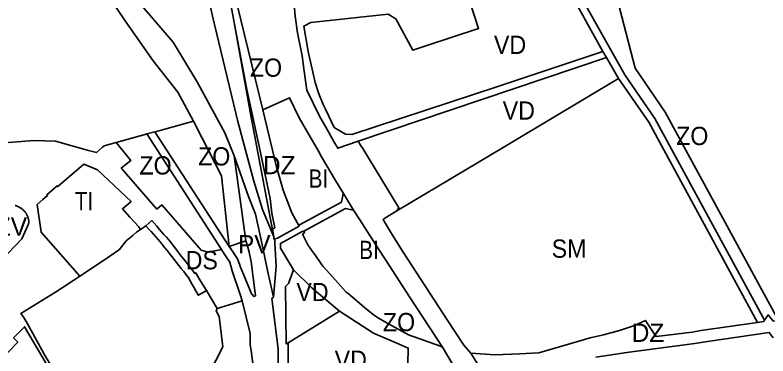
# Model space of a CAD drawing. Extents: x -650451 to -642268, y -1075216 to -1066610.
# Drawn here: x -648056 to -647438, y -1069866 to -1069586 of the extents above; entities that cross this region are included whole.
import ezdxf

# ---------------------------------------------------------------- set-up
doc = ezdxf.new("R2010")
doc.units = 0
doc.header["$LTSCALE"] = 6
doc.layers.add('1', color=7, linetype='Continuous', lineweight=35)
doc.layers.add('2', color=7, linetype='Continuous')
doc.layers.add('3', color=7, linetype='Continuous')

msp = doc.modelspace()

# ---------------------------------------------------------------- linework, layer by layer
at = {"layer": '1'}
for p, q in [((-647570.37, -1069621.18), (-647774.11, -1069689.64)), ((-647570.37, -1069621.18), (-647573.15, -1069616.16)), ((-647570.37, -1069621.18), (-647560.36, -1069638.39)), ((-647866.4, -1069771.43), (-647875.82, -1069701.85)), ((-647843.449, -1069768.251), (-647843.443, -1069768.293)), ((-647866.4, -1069771.43), (-647879.96, -1069776.1)), ((-647889.83, -1069826.99), (-647898.71, -1069812.26)), ((-647831.62, -1069854.99), (-647789.55, -1069829.12))]:
    msp.add_line(p, q, dxfattribs=at)
for points in [[(-647843.443, -1069768.293), (-647852.78, -1069745.71), (-647859.722, -1069722.428), (-647872.87, -1069673.56), (-647893.75, -1069587.08), (-647922.04, -1069459.71), (-647925.16, -1069445.68), (-647928.41, -1069431.03), (-647945.28, -1069355.1), (-647956.27, -1069311.58), (-647974.81, -1069246.86), (-647977.29, -1069238.21), (-648005.47, -1069192.09), (-648024.02, -1069174.7), (-648034.421, -1069167.61)], [(-648290.39, -1069177.69), (-648280.46, -1069187.61), (-648147.81, -1069355.26), (-648143.81, -1069359.39), (-648116.93, -1069393.25), (-648052.62, -1069476.32), (-647995.61, -1069549.95), (-647984.36, -1069564.49), (-647980.21, -1069569.97), (-647974.74, -1069577.39), (-647962.93, -1069594.39), (-647942.48, -1069623.82), (-647922.32, -1069649.56), (-647909.25, -1069673.35)], [(-647774.11, -1069689.64), (-647790.88, -1069695.49), (-647793.77, -1069690.4), (-647800.98, -1069677.69), (-647805.51, -1069669.7), (-647816.39, -1069647.74), (-647818.42, -1069632.36), (-647820.07, -1069619.78), (-647823.88, -1069600.72), (-647825.89, -1069587.19), (-647827.1, -1069574.34), (-647827.22, -1069571.45), (-647827.31, -1069569.36), (-647827.71, -1069559.64), (-647828.17, -1069548.8), (-647828.68, -1069536.6), (-647824.5, -1069467.9), (-647821.93, -1069425.59), (-647819.51, -1069386.41), (-647814.57, -1069305.32), (-647811.084, -1069257.214)], [(-647887.087, -1069527.229), (-647887.649, -1069528.021), (-647876.056, -1069592.232)], [(-647852.44, -1069664.03), (-647873.43, -1069577.87), (-647887.087, -1069527.229)], [(-647606.53, -1069555.98), (-647600.891, -1069566.14), (-647573.15, -1069616.16)], [(-647875.82, -1069701.85), (-647883.51, -1069682.71), (-647906.16, -1069641.48), (-647925.99, -1069608.57), (-647958.34, -1069570.698)], [(-647600.891, -1069566.14), (-647679.81, -1069574.91), (-647682.22, -1069576.19), (-647675.26, -1069597.24), (-647718.71, -1069611.6), (-647727.55, -1069614.52), (-647729.31, -1069615.1), (-647743.25, -1069589.24), (-647749.4, -1069585.37), (-647813.02, -1069592.44), (-647818.74, -1069595.32), (-647815.08, -1069616.01), (-647809.52, -1069641.61), (-647806.38, -1069650.88), (-647802.83, -1069659.58), (-647800.97, -1069663.54), (-647793.91, -1069678.36), (-647784.61, -1069683.92), (-647779.26, -1069684.27), (-647659.57, -1069644.72), (-647573.15, -1069616.16)], [(-647563.104, -1069566.28), (-647592.199, -1069569.411), (-647555.266, -1069635.207), (-647530.471, -1069671.013), (-647440.459, -1069836.56)], [(-647563.104, -1069566.28), (-647546.777, -1069629.901), (-647521.943, -1069665.763), (-647428.993, -1069836.714)], [(-647843.449, -1069768.251), (-647844.371, -1069761.991), (-647842.438, -1069760.647), (-647845.086, -1069748.753), (-647846.484, -1069736.663), (-647855.158, -1069695.232), (-647865.69, -1069647.32), (-647876.056, -1069592.232)], [(-647876.056, -1069592.232), (-647862.266, -1069668.613), (-647843.449, -1069768.251)], [(-647560.36, -1069638.39), (-647674.901, -1069706.701), (-647742.36, -1069746.93)], [(-647560.36, -1069638.39), (-647535.588, -1069674.163), (-647446.322, -1069838.338)], [(-647786.31, -1069732.58), (-647792.63, -1069721.98), (-647800.63, -1069708.57), (-647804.21, -1069702.56), (-647806.81, -1069698.01), (-647822.48, -1069670.62), (-647830.41, -1069654.06), (-647852.44, -1069664.03)], [(-647822.54, -1069759.29), (-647828.61, -1069748.41), (-647835.76, -1069730.01), (-647841.26, -1069710.69), (-647852.44, -1069664.03)], [(-647941.05, -1069682.01), (-647937.88, -1069681.15), (-647909.25, -1069673.35)], [(-647909.25, -1069673.35), (-647902.18, -1069687.23), (-647886.43, -1069718.16), (-647879.96, -1069776.1)], [(-647886.49, -1069778.43), (-647947.59, -1069683.79), (-647941.05, -1069682.01), (-647879.96, -1069776.1)], [(-648113.96, -1069702.201), (-648098.18, -1069697.68), (-648089.7, -1069695.52), (-648075.43, -1069691.89), (-648040.14, -1069689.07), (-648022.75, -1069689.72), (-647995.54, -1069697.22), (-647989.07, -1069699), (-647984.08, -1069694.48), (-647982.78, -1069693.38), (-647972.92, -1069690.69)], [(-647972.92, -1069690.69), (-647948.27, -1069683.98), (-647947.59, -1069683.79)], [(-647886.49, -1069778.43), (-647897.27, -1069780.63), (-647903.06, -1069779.06), (-647935.39, -1069741.96), (-647939.4, -1069745.45), (-647967.98, -1069712.66), (-647968.73, -1069711.82), (-647960.71, -1069705.53), (-647972.92, -1069690.69)], [(-647774.11, -1069689.64), (-647772.13, -1069692.89), (-647770.38, -1069695.75), (-647740.74, -1069744.24), (-647742.36, -1069746.93)], [(-647875.82, -1069701.85), (-647864.19, -1069735.12), (-647858.44, -1069749.43), (-647852.63, -1069775.7), (-647848.71, -1069795.69), (-647843.74, -1069817.63)], [(-647952.84, -1069762.02), (-647954.36, -1069760.07), (-647961.6, -1069751.97), (-647967.65, -1069745.21), (-647960.63, -1069739.15), (-647988.22, -1069713.07), (-647999.45, -1069708.58), (-648020.77, -1069727), (-648021.34, -1069726.35), (-648029.72, -1069733.61), (-648029.16, -1069734.25), (-648033.13, -1069737.67), (-648037.78, -1069741.69), (-648034.44, -1069764.42), (-648002.79, -1069800.48)], [(-647786.31, -1069732.58), (-647786.69, -1069734.22), (-647787.93, -1069739.64), (-647822.18, -1069758.26), (-647822.54, -1069759.29)], [(-647778.08, -1069746.18), (-647779.73, -1069743.63), (-647786.31, -1069732.58)], [(-648124.28, -1069847.04), (-648050.23, -1069769.71), (-648045.277, -1069758.785), (-648045.1, -1069758.377), (-648044.953, -1069757.961), (-648044.835, -1069757.535), (-648044.744, -1069757.101), (-648044.681, -1069756.66), (-648044.643, -1069756.213), (-648044.63, -1069755.762), (-648044.64, -1069755.308), (-648044.673, -1069754.851), (-648044.727, -1069754.393), (-648044.801, -1069753.935), (-648044.895, -1069753.479), (-648045.006, -1069753.024), (-648045.135, -1069752.573), (-648045.279, -1069752.126), (-648045.438, -1069751.685), (-648045.61, -1069751.25), (-648045.795, -1069750.824), (-648045.989, -1069750.409), (-648046.193, -1069750.006), (-648046.406, -1069749.614), (-648046.629, -1069749.232), (-648046.863, -1069748.861), (-648047.107, -1069748.499), (-648047.363, -1069748.147), (-648047.63, -1069747.803), (-648047.91, -1069747.468), (-648048.201, -1069747.14), (-648048.506, -1069746.819), (-648048.824, -1069746.506), (-648049.155, -1069746.198), (-648049.5, -1069745.896), (-648049.86, -1069745.599), (-648050.234, -1069745.307), (-648050.623, -1069745.019), (-648051.022, -1069744.74), (-648051.421, -1069744.474), (-648051.822, -1069744.222), (-648052.223, -1069743.983), (-648052.626, -1069743.758), (-648053.03, -1069743.544), (-648053.436, -1069743.343), (-648053.842, -1069743.154), (-648054.251, -1069742.976), (-648054.66, -1069742.809), (-648055.072, -1069742.653), (-648055.485, -1069742.507), (-648055.9, -1069742.371)], [(-647818.73, -1069763.53), (-647784.54, -1069744.82), (-647779.25, -1069745.93), (-647778.08, -1069746.18)], [(-647778.08, -1069746.18), (-647772.88, -1069754.18), (-647764.6, -1069766.94), (-647756.51, -1069779.4), (-647748.29, -1069792.07), (-647731.89, -1069817.33), (-647704.99, -1069858.7)], [(-647742.36, -1069746.93), (-647752.32, -1069752.95), (-647753.7, -1069753.9), (-647751.66, -1069757.12), (-647745.84, -1069766.71), (-647737.17, -1069780.85), (-647700.58, -1069837.2), (-647687.45, -1069857.15), (-647681.51, -1069863.72)], [(-647948.35, -1069759.15), (-647943.52, -1069754.88), (-647939.43, -1069759.53), (-647937.47, -1069761.75), (-647933.58, -1069766.18), (-647931.63, -1069768.39), (-647929.62, -1069770.68), (-647927.69, -1069773.17), (-647922.17, -1069780.28), (-647920.21, -1069782.81), (-647916.41, -1069787.71), (-647910.53, -1069795.3), (-647908.28, -1069798.2), (-647907.46, -1069797.74), (-647905.71, -1069800.64), (-647904.01, -1069803.47), (-647900.63, -1069809.06), (-647898.71, -1069812.26)], [(-647952.84, -1069762.02), (-647956.11, -1069764.33), (-647959.2, -1069767), (-647964.57, -1069771.53), (-647970.38, -1069778.79), (-647970.9, -1069779.13), (-647981.64, -1069786.5), (-648002.79, -1069800.48)], [(-647948.35, -1069759.15), (-647949.6, -1069759.86), (-647952.84, -1069762.02)], [(-647898.71, -1069812.26), (-647899.91, -1069812.94), (-647901.54, -1069813.87), (-647905.39, -1069816.05), (-647905.87, -1069815.22), (-647907.16, -1069812.97), (-647908.85, -1069810.03), (-647910.48, -1069807.21), (-647912.12, -1069804.35), (-647913.84, -1069801.36), (-647915.44, -1069799.27), (-647917.38, -1069796.72), (-647919.35, -1069794.14), (-647921.28, -1069791.59), (-647921.48, -1069791.74), (-647923.43, -1069789.21), (-647925.33, -1069786.75), (-647930.91, -1069779.5), (-647932.77, -1069777.08), (-647934.69, -1069774.59), (-647936.43, -1069772.63), (-647940.33, -1069768.21), (-647942.29, -1069766), (-647944.24, -1069763.79), (-647946.23, -1069761.55), (-647948.35, -1069759.15)], [(-647822.54, -1069759.29), (-647840.49, -1069769.3), (-647842.55, -1069769.78), (-647842.54, -1069770.346)], [(-647818.73, -1069763.53), (-647820.09, -1069763.65), (-647826.95, -1069767.48), (-647838, -1069773.63), (-647837.93, -1069777.45), (-647827.16, -1069795.32)], [(-647818.73, -1069763.53), (-647818.28, -1069764.99), (-647819.78, -1069765.84), (-647815.36, -1069774.66), (-647811.65, -1069780.12), (-647809.71, -1069782.79), (-647804.02, -1069791.01), (-647802.92, -1069792.37), (-647797.33, -1069798.65), (-647792.84, -1069803.65), (-647783.96, -1069813.49), (-647782.72, -1069814.46), (-647770.77, -1069824.47), (-647768.63, -1069826.34), (-647760.79, -1069832.61), (-647758.25, -1069834.21), (-647752.25, -1069837.95), (-647732.93, -1069848.5), (-647706.44, -1069857.98), (-647704.99, -1069858.7)], [(-647843.443, -1069768.293), (-647843.337, -1069769.013), (-647842.798, -1069770.477), (-647842.54, -1069770.346)], [(-647879.96, -1069776.1), (-647876.87, -1069780.85), (-647872.99, -1069786.83), (-647870.77, -1069792.99), (-647861.35, -1069815.39), (-647861.27, -1069815.59), (-647859.7, -1069817.18), (-647858.35, -1069816.5), (-647862.06, -1069788.75), (-647863.66, -1069780.72), (-647864.84, -1069776.71), (-647866.4, -1069771.43)], [(-647843.74, -1069817.63), (-647841.402, -1069792.351), (-647842.489, -1069773.282), (-647842.54, -1069770.346)], [(-647869.45, -1069820.63), (-647870.84, -1069816.36), (-647877.49, -1069795.99), (-647879.63, -1069789.06), (-647883.51, -1069783.05), (-647886.49, -1069778.43)], [(-647958.13, -1069974.97), (-647993.37, -1069922.95), (-648011.98, -1069897.09), (-648030.85, -1069866.2), (-648045.74, -1069839.57), (-648048.56, -1069834.42), (-648051.03, -1069831.04), (-648022.75, -1069813.67), (-648017.19, -1069809.99), (-648007.72, -1069803.73), (-648002.79, -1069800.48)], [(-647831.62, -1069854.99), (-647833.172, -1069855.944), (-647833.91, -1069808.91), (-647831.32, -1069806.56), (-647827.16, -1069795.32)], [(-647789.55, -1069829.12), (-647811.83, -1069810.39), (-647827.16, -1069795.32)], [(-647815.2, -1069946.41), (-647816.05, -1069948.55), (-647817.39, -1069951.94), (-647819.81, -1069955.62), (-647839.73, -1069913), (-647839.71, -1069910.43), (-647839.88, -1069860.04), (-647844.97, -1069818.73), (-647843.74, -1069817.63)], [(-647869.45, -1069820.63), (-647883.66, -1069825.06), (-647889.83, -1069826.99)], [(-647869.45, -1069820.63), (-647862.69, -1069847.43), (-647862.69, -1069856.72), (-647862.05, -1069861.48), (-647858.4, -1069889.05), (-647857.31, -1069921.08), (-647858.77, -1069940.78), (-647860.25, -1069956.63), (-647861.12, -1069970.21), (-647865.08, -1070001.86), (-647859.17, -1070011.72), (-647860.76, -1070027.86), (-647863.6, -1070070.49), (-647867.36, -1070127.21), (-647873.97, -1070156.58)], [(-647889.83, -1069826.99), (-647890.85, -1069828.89), (-647888.27, -1069833.43), (-647885.2, -1069858.5), (-647902.22, -1069891.35)], [(-647789.55, -1069829.12), (-647761.54, -1069847.24), (-647740.46, -1069856.29), (-647733.06, -1069859.46), (-647733.71, -1069886.65)], [(-647681.51, -1069863.72), (-647661.79, -1069864.92), (-647641.78, -1069864.26), (-647625.83, -1069863.19), (-647593.07, -1069853.74), (-647583.62, -1069851.13), (-647572.63, -1069848.63), (-647559.47, -1069844.92), (-647547.12, -1069840.87), (-647538.34, -1069836.68), (-647536.82, -1069838.87), (-647531.33, -1069847.23), (-647529.5, -1069849.99), (-647500.03, -1069846.28), (-647492.76, -1069845.02), (-647446.322, -1069838.338)], [(-647446.322, -1069838.338), (-647441.19, -1069837.6), (-647440.459, -1069836.56)], [(-647440.459, -1069836.56), (-647439.63, -1069835.38), (-647437.46, -1069832.27), (-647435.36, -1069834.84), (-647433.32, -1069837.33), (-647428.993, -1069836.714)], [(-648078.54, -1069880.01), (-648053.61, -1069854.64), (-648057.11, -1069851.12), (-648048.08, -1069841.95), (-648032.94, -1069867.46), (-648015.11, -1069898.98), (-647994.71, -1069930.53)], [(-647433.48, -1069851.02), (-647436.61, -1069846.52), (-647487.26, -1069854), (-647497.78, -1069855.56), (-647555.79, -1069863.4), (-647557.18, -1069863.59), (-647579.04, -1069866.8)], [(-647815.2, -1069946.41), (-647828.12, -1069924.51), (-647825.63, -1069923.6), (-647831.27, -1069911.02), (-647831.35, -1069898.79), (-647831.62, -1069854.99)], [(-647694.63, -1069876.07), (-647696.25, -1069873.35), (-647704.99, -1069858.7)], [(-647681.51, -1069863.72), (-647672.09, -1069878.85), (-647637.08, -1069934.31)]]:
    msp.add_lwpolyline(points, dxfattribs=at)

# ---------------------------------------------------------------- texts
at = {"layer": '2'}
for s, width, p in [('VD', 0.95, (-647662.661, -1069618.152)), ('ZO', 0.95, (-647905.57, -1069709.63)), ('ZO', 0.95, (-647953.76, -1069717.04)), ('BI', 0.85, (-647814.816, -1069727.895)), ('TI', 0.85, (-648006.8, -1069746.35)), ('BI', 0.85, (-647773.327, -1069786.425)), ('DS', 0.95, (-647915.789, -1069794.831)), ('VD', 0.95, (-647793.458, -1069876.412))]:
    msp.add_text(s, height=15, dxfattribs=dict(at, width=width)).set_placement(p)
for s, p in [('ZV', (-648071.68, -1069767.27)), ('PV', (-647872.819, -1069781.778)), ('DZ', (-647549.528, -1069854.349))]:
    msp.add_text(s, height=15, dxfattribs=at).set_placement(p)
at = {"layer": '3', "width": 0.95}
for s, p in [('ZO', (-647863.042, -1069636.843)), ('VD', (-647655.477, -1069672.083)), ('ZO', (-647513.034, -1069692.88)), ('SM', (-647615.257, -1069785.33)), ('VD', (-647824.859, -1069820.928)), ('ZO', (-647753.829, -1069845.599))]:
    msp.add_text(s, height=15, dxfattribs=at).set_placement(p)
at = {"layer": '3'}
msp.add_text('DZ', height=15, dxfattribs=at).set_placement((-647852.294, -1069716.788))

doc.saveas('drawing.dxf')
